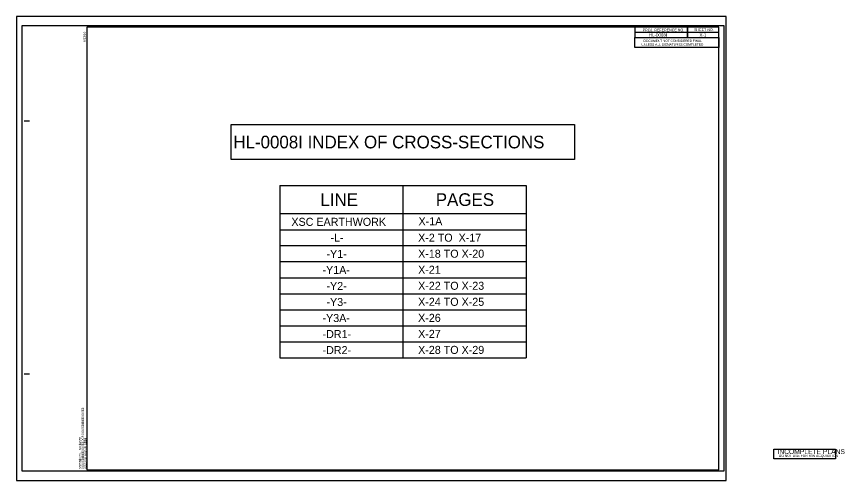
# Model space of a CAD drawing. Extents: x 11196 to 11588, y 11730 to 11950.
import ezdxf

# ---------------------------------------------------------------- set-up
doc = ezdxf.new("R2010")
doc.units = 0
for name, color, linetype in [('Prop XS Project Number', 7, 'Continuous'), ('Prop XS Sheet Number', 7, 'Continuous'), ('Sheet Border Standard 30in CELL', 7, 'Continuous'), ('Sheet Cross Section CELL', 7, 'Continuous'), ('Sheet Data Field CELL', 7, 'Continuous'), ('Sheet Detail CELL', 7, 'Continuous'), ('Sheet Plan CELL', 7, 'Continuous'), ('Sheet Plot Border Inside CELL', 7, 'Continuous'), ('Sheet Plot Border Outside CELL', 7, 'Continuous'), ('Sheet Sticker Exception Certification CELL', 7, 'Continuous'), ('Sheet Sticker Incomplete CELL', 7, 'Continuous')]:
    doc.layers.add(name, color=color, linetype=linetype)

msp = doc.modelspace()

# ---------------------------------------------------------------- linework, layer by layer
at = {"layer": 'Sheet Border Standard 30in CELL'}
for p, q in [((11199.4, 11900.13), (11201.9, 11900.13)), ((11199.4, 11780.17), (11201.9, 11780.17))]:
    msp.add_line(p, q, dxfattribs=at)
msp.add_lwpolyline([(11529, 11944.62), (11229.09, 11944.62), (11229.09, 11734.68), (11529, 11734.68)], close=True, dxfattribs=at)
at = {"layer": 'Sheet Cross Section CELL'}
for p, q in [((11489, 11942.12), (11489, 11939.62)), ((11529, 11942.11), (11489, 11942.11)), ((11514, 11944.62), (11514, 11939.62)), ((11514, 11939.62), (11514, 11944.62)), ((11489, 11939.62), (11529, 11939.62))]:
    msp.add_line(p, q, dxfattribs=at)
msp.add_lwpolyline([(11529, 11944.62), (11489, 11944.62), (11489, 11939.62), (11529, 11939.62)], close=True, dxfattribs=at)
at = {"layer": 'Sheet Detail CELL'}
for p, q in [((11320.65, 11869.45), (11320.65, 11787.81)), ((11320.65, 11869.45), (11379.05, 11869.45)), ((11379.05, 11869.45), (11379.05, 11787.81)), ((11379.05, 11869.45), (11437.44, 11869.45)), ((11437.44, 11869.45), (11437.44, 11787.81)), ((11320.65, 11856.21), (11379.05, 11856.21)), ((11379.05, 11856.21), (11437.44, 11856.21)), ((11320.65, 11848.52), (11437.44, 11848.52)), ((11320.65, 11841.01), (11379.05, 11841.01)), ((11379.05, 11841.01), (11437.44, 11841.01)), ((11320.65, 11833.41), (11379.05, 11833.41)), ((11379.05, 11833.41), (11437.44, 11833.41)), ((11320.65, 11825.81), (11379.05, 11825.81)), ((11379.05, 11825.81), (11437.44, 11825.81)), ((11320.65, 11818.21), (11379.05, 11818.21)), ((11379.05, 11818.21), (11437.44, 11818.21)), ((11320.65, 11810.61), (11437.44, 11810.61)), ((11320.65, 11810.61), (11379.05, 11810.61)), ((11320.65, 11803.01), (11437.44, 11803.01)), ((11320.65, 11795.41), (11437.44, 11795.41)), ((11320.65, 11787.81), (11437.44, 11787.81))]:
    msp.add_line(p, q, dxfattribs=at)
msp.add_lwpolyline([(11297.62, 11898.39), (11460.47, 11898.39), (11460.47, 11881.85), (11297.62, 11881.85)], close=True, dxfattribs=at)
at = {"layer": 'Sheet Plot Border Inside CELL'}
msp.add_lwpolyline([(11531.5, 11945.13), (11198.3, 11945.13), (11198.3, 11734.17), (11531.5, 11734.17)], close=True, dxfattribs=at)
at = {"layer": 'Sheet Plot Border Outside CELL'}
msp.add_lwpolyline([(11532.4, 11949.62), (11195.7, 11949.62), (11195.7, 11729.68), (11532.4, 11729.68)], close=True, dxfattribs=at)
at = {"layer": 'Sheet Sticker Exception Certification CELL'}
for p, q in [((11489, 11934.92), (11489, 11939.62)), ((11489, 11939.62), (11529, 11939.62)), ((11529, 11939.61), (11529, 11934.92)), ((11529, 11934.92), (11489, 11934.92))]:
    msp.add_line(p, q, dxfattribs=at)
at = {"layer": 'Sheet Sticker Incomplete CELL'}
msp.add_lwpolyline([(11554.96, 11739.87), (11554.96, 11744.57), (11584.36, 11744.57), (11584.36, 11739.87)], close=True, dxfattribs=at)

# ---------------------------------------------------------------- texts
at = {"layer": 'Prop XS Project Number'}
msp.add_text('HL-0008I', height=1.5, dxfattribs=at).set_placement((11495.8, 11940.11))
at = {"layer": 'Prop XS Sheet Number'}
msp.add_text('X-1', height=1.5, dxfattribs=at).set_placement((11519.76, 11940.11))
at = {"layer": 'Sheet Cross Section CELL'}
for s, p in [('PROJ. REFERENCE NO.', (11492.77, 11942.61)), ('SHEET NO.', (11517.19, 11942.74))]:
    msp.add_text(s, height=1.25, dxfattribs=at).set_placement(p)
at = {"layer": 'Sheet Data Field CELL'}
for s, height, p in [('HL-0008I INDEX OF CROSS-SECTIONS', 6, (11298.58, 11887.12)), ('LINE', 6, (11339.87, 11859.83)), ('PAGES', 6, (11394.63, 11859.83)), ('XSC EARTHWORK', 3.8, (11326.12, 11850.39)), ('X-1A', 3.8, (11386.43, 11850.65)), ('-L-', 3.8, (11344.66, 11842.88)), ('X-2 TO  X-17', 3.8, (11386.25, 11842.88)), ('X-18 TO X-20', 3.8, (11386.25, 11835.28)), ('-Y1-', 3.8, (11342.77, 11835.19)), ('-Y1A-', 3.8, (11340.89, 11827.59)), ('X-21', 3.8, (11386.25, 11827.68)), ('-Y2-', 3.8, (11342.77, 11819.99)), ('X-22 TO X-23', 3.8, (11386.25, 11820.08)), ('-Y3-', 3.8, (11342.77, 11812.39)), ('X-24 TO X-25', 3.8, (11386.25, 11812.48)), ('-Y3A-', 3.8, (11340.89, 11804.79)), ('X-26', 3.8, (11386.25, 11804.88)), ('-DR1-', 3.8, (11340.89, 11797.19)), ('X-27', 3.8, (11386.25, 11797.28)), ('-DR2-', 3.8, (11340.89, 11789.59)), ('X-28 TO X-29', 3.8, (11386.25, 11789.68))]:
    msp.add_text(s, height=height, dxfattribs=at).set_placement(p)
at = {"layer": 'Sheet Plan CELL'}
for s, height, p in [('6/23/16', 1.05, (11228.44, 11937.6)), ('$$$$$$$$$$$$$$$$DGN$$$$$$$$$$$$$$$$', 1.0497, (11227.56, 11735.15)), ('$$$$$$SYSTIME$$$$$', 1.0497, (11226.35, 11735.15)), ('$$$$USERNAME$$$$', 1.0497, (11228.87, 11735.15))]:
    msp.add_text(s, height=height, rotation=90, dxfattribs=at).set_placement(p)
at = {"layer": 'Sheet Sticker Exception Certification CELL'}
for s, p in [('DOCUMENT NOT CONSIDERED FINAL', (11493.21, 11937.55)), ('UNLESS ALL SIGNATURES COMPLETED', (11492.2, 11935.79))]:
    msp.add_text(s, height=1.0998, dxfattribs=at).set_placement(p)
at = {"layer": 'Sheet Sticker Incomplete CELL'}
for s, height, p in [('INCOMPLETE PLANS', 2.3036, (11556.75, 11742.21)), ('DO NOT USE FOR R/W ACQUISITION', 1.1518, (11557.4, 11740.82))]:
    msp.add_text(s, height=height, dxfattribs=at).set_placement(p)

doc.saveas('drawing.dxf')
